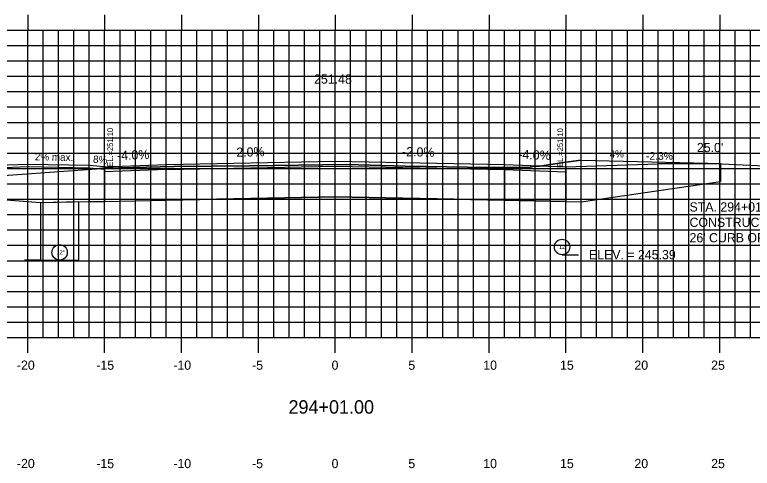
# Model space of a CAD drawing. Extents: x 859129 to 859299, y 366268 to 366378.
# Drawn here: x 859191.61 to 859239.58, y 366298.73 to 366328.24 of the extents above; entities that cross this region are included whole.
import ezdxf

# ---------------------------------------------------------------- set-up
doc = ezdxf.new("R2010")
doc.units = 0
for name, color, linetype in [('ANNOTATION', 7, 'Continuous'), ('D_Roadway_Centerline_Text', 7, 'Continuous'), ('D_Roadway_Drive_Gravel_LT', 7, 'Continuous'), ('D_Roadway_Drive_Gravel_RT', 7, 'Continuous'), ('D_Roadway_Drive_SubGrade', 7, 'Continuous'), ('D_Roadway_Edge_Shoulder', 7, 'Continuous'), ('D_Roadway_SubGrade', 7, 'Continuous'), ('D_Text_Monospaced', 7, 'Continuous'), ('D_Text_Standard', 7, 'Continuous'), ('H_V ANNOTATION', 7, 'Continuous'), ('JUNK COM EXC', 7, 'Continuous'), ('junk strct exc', 7, 'Continuous'), ('MAJOR', 7, 'Continuous'), ('MINOR', 7, 'Continuous'), ('PDRAIN', 7, 'Continuous'), ('S_Roadway_Centerline', 7, 'Continuous')]:
    doc.layers.add(name, color=color, linetype=linetype)

msp = doc.modelspace()

# ---------------------------------------------------------------- linework, layer by layer
at = {"layer": 'D_Roadway_Drive_Gravel_LT'}
for p, q in [((859192.463, 366318.501), (859189.459, 366318.381)), ((859192.47, 366318.334), (859189.459, 366318.214)), ((859196.455, 366318.254), (859192.455, 366318.334)), ((859196.463, 366318.421), (859192.463, 366318.501)), ((859197.459, 366318.174), (859196.455, 366318.254)), ((859197.463, 366318.341), (859196.463, 366318.421)), ((859197.463, 366318.341), (859197.463, 366318.007))]:
    msp.add_line(p, q, dxfattribs=at)
at = {"layer": 'D_Roadway_Drive_Gravel_RT'}
msp.add_line((859227.462, 366318.341), (859233.462, 366318.546), dxfattribs=at)
at = {"layer": 'D_Roadway_Drive_SubGrade'}
for p, q in [((859237.508, 366318.546), (859233.462, 366318.546)), ((859237.508, 366318.546), (859237.508, 366317.379)), ((859228.462, 366316.068), (859237.508, 366317.379)), ((859193.284, 366316.004), (859184.612, 366316.674)), ((859197.459, 366316.087), (859193.284, 366316.004)), ((859227.462, 366316.088), (859228.462, 366316.068))]:
    msp.add_line(p, q, dxfattribs=at)
at = {"layer": 'D_Roadway_Edge_Shoulder'}
msp.add_line((859227.463, 366318.341), (859227.464, 366318.007), dxfattribs=at)
msp.add_lwpolyline([(859197.463, 366318.341), (859201.463, 366318.501), (859212.463, 366318.721), (859223.463, 366318.501), (859227.462, 366318.341)], dxfattribs=at)
at = {"layer": 'D_Roadway_SubGrade'}
for points in [[(859201.463, 366318.167), (859197.463, 366318.007), (859197.463, 366316.087), (859201.463, 366316.167)], [(859201.463, 366316.167), (859201.463, 366318.167), (859212.463, 366318.387), (859223.463, 366318.167), (859223.463, 366316.167), (859212.463, 366316.387)], [(859223.463, 366318.167), (859227.464, 366318.007), (859227.464, 366316.087), (859223.463, 366316.167)]]:
    msp.add_lwpolyline(points, close=True, dxfattribs=at)
at = {"layer": 'D_Text_Standard'}
for points in [[(859227.212, 366312.626), (859227.599, 366312.626), (859228.279, 366312.626)], [(859193.284, 366312.276), (859192.927, 366312.276), (859192.247, 366312.276)]]:
    msp.add_lwpolyline(points, dxfattribs=at)
at = {"layer": 'JUNK COM EXC'}
msp.add_lwpolyline([(859228.456, 366318.772), (859228.452, 366318.772), (859227.301, 366318.615), (859225.757, 366318.383), (859225.438, 366318.377), (859225.019, 366318.299), (859223.494, 366318.328), (859222.407, 366318.303), (859217.013, 366318.39), (859213.218, 366318.491), (859206.908, 366318.407), (859201.989, 366318.366), (859197.482, 366318.259), (859197.347, 366318.256), (859197.329, 366318.256), (859196.931, 366318.222), (859196.459, 366318.189), (859196.459, 366316.067), (859201.463, 366316.167), (859212.463, 366316.387), (859223.463, 366316.167), (859228.462, 366316.068), (859228.456, 366318.772)], dxfattribs=at)
at = {"layer": 'junk strct exc'}
msp.add_lwpolyline([(859193.284, 366316.004), (859193.284, 366312.276), (859195.784, 366312.276), (859195.784, 366316.054)], close=True, dxfattribs=at)
at = {"layer": 'MAJOR'}
for p, q in [((859192.462, 366328.238), (859192.462, 366327.236)), ((859197.462, 366328.238), (859197.462, 366327.236)), ((859202.462, 366328.238), (859202.462, 366327.236)), ((859207.462, 366328.238), (859207.462, 366327.236)), ((859212.462, 366328.238), (859212.462, 366327.236)), ((859217.462, 366328.238), (859217.462, 366327.236)), ((859222.462, 366328.238), (859222.462, 366327.236)), ((859227.462, 366328.238), (859227.462, 366327.236)), ((859232.462, 366328.238), (859232.462, 366327.236)), ((859237.462, 366328.238), (859237.462, 366327.236)), ((859142.462, 366327.236), (859282.462, 366327.236)), ((859142.462, 366327.236), (859282.462, 366327.236)), ((859192.462, 366307.236), (859192.462, 366327.236)), ((859197.462, 366307.236), (859197.462, 366327.236)), ((859202.462, 366307.236), (859202.462, 366327.236)), ((859207.462, 366307.236), (859207.462, 366327.236)), ((859212.462, 366307.236), (859212.462, 366327.236)), ((859217.462, 366307.236), (859217.462, 366327.236)), ((859222.462, 366307.236), (859222.462, 366327.236)), ((859227.462, 366307.236), (859227.462, 366327.236)), ((859232.462, 366307.236), (859232.462, 366327.236)), ((859237.462, 366307.236), (859237.462, 366327.236)), ((859142.462, 366322.236), (859282.462, 366322.236)), ((859142.462, 366317.236), (859282.462, 366317.236)), ((859142.462, 366312.236), (859282.462, 366312.236)), ((859142.462, 366307.236), (859282.462, 366307.236)), ((859142.462, 366307.236), (859282.462, 366307.236)), ((859192.462, 366306.234), (859192.462, 366307.236)), ((859197.462, 366306.234), (859197.462, 366307.236)), ((859202.462, 366306.234), (859202.462, 366307.236)), ((859207.462, 366306.234), (859207.462, 366307.236)), ((859212.462, 366306.234), (859212.462, 366307.236)), ((859217.462, 366306.234), (859217.462, 366307.236)), ((859222.462, 366306.234), (859222.462, 366307.236)), ((859227.462, 366306.234), (859227.462, 366307.236)), ((859232.462, 366306.234), (859232.462, 366307.236)), ((859237.462, 366306.234), (859237.462, 366307.236))]:
    msp.add_line(p, q, dxfattribs=at)
at = {"layer": 'MINOR'}
for p, q in [((859193.462, 366307.236), (859193.462, 366327.236)), ((859194.462, 366307.236), (859194.462, 366327.236)), ((859195.462, 366307.236), (859195.462, 366327.236)), ((859196.462, 366307.236), (859196.462, 366327.236)), ((859198.462, 366307.236), (859198.462, 366327.236)), ((859199.462, 366307.236), (859199.462, 366327.236)), ((859200.462, 366307.236), (859200.462, 366327.236)), ((859201.462, 366307.236), (859201.462, 366327.236)), ((859203.462, 366307.236), (859203.462, 366327.236)), ((859204.462, 366307.236), (859204.462, 366327.236)), ((859205.462, 366307.236), (859205.462, 366327.236)), ((859206.462, 366307.236), (859206.462, 366327.236)), ((859208.462, 366307.236), (859208.462, 366327.236)), ((859209.462, 366307.236), (859209.462, 366327.236)), ((859210.462, 366307.236), (859210.462, 366327.236)), ((859211.462, 366307.236), (859211.462, 366327.236)), ((859213.462, 366307.236), (859213.462, 366327.236)), ((859214.462, 366307.236), (859214.462, 366327.236)), ((859215.462, 366307.236), (859215.462, 366327.236)), ((859216.462, 366307.236), (859216.462, 366327.236)), ((859218.462, 366307.236), (859218.462, 366327.236)), ((859219.462, 366307.236), (859219.462, 366327.236)), ((859220.462, 366307.236), (859220.462, 366327.236)), ((859221.462, 366307.236), (859221.462, 366327.236)), ((859223.462, 366307.236), (859223.462, 366327.236)), ((859224.462, 366307.236), (859224.462, 366327.236)), ((859225.462, 366307.236), (859225.462, 366327.236)), ((859226.462, 366307.236), (859226.462, 366327.236)), ((859228.462, 366307.236), (859228.462, 366327.236)), ((859229.462, 366307.236), (859229.462, 366327.236)), ((859230.462, 366307.236), (859230.462, 366327.236)), ((859231.462, 366307.236), (859231.462, 366327.236)), ((859233.462, 366307.236), (859233.462, 366327.236)), ((859234.462, 366307.236), (859234.462, 366327.236)), ((859235.462, 366307.236), (859235.462, 366327.236)), ((859236.462, 366307.236), (859236.462, 366327.236)), ((859238.462, 366307.236), (859238.462, 366327.236)), ((859239.462, 366307.236), (859239.462, 366327.236)), ((859142.462, 366326.236), (859282.462, 366326.236)), ((859142.462, 366325.236), (859282.462, 366325.236)), ((859142.462, 366324.236), (859282.462, 366324.236)), ((859142.462, 366323.236), (859282.462, 366323.236)), ((859142.462, 366321.236), (859282.462, 366321.236)), ((859142.462, 366320.236), (859282.462, 366320.236)), ((859142.462, 366319.236), (859282.462, 366319.236)), ((859142.462, 366318.236), (859282.462, 366318.236)), ((859142.462, 366316.236), (859282.462, 366316.236)), ((859142.462, 366315.236), (859282.462, 366315.236)), ((859142.462, 366314.236), (859282.462, 366314.236)), ((859142.462, 366313.236), (859282.462, 366313.236)), ((859142.462, 366311.236), (859282.462, 366311.236)), ((859142.462, 366310.236), (859282.462, 366310.236)), ((859142.462, 366309.236), (859282.462, 366309.236)), ((859142.462, 366308.236), (859282.462, 366308.236))]:
    msp.add_line(p, q, dxfattribs=at)
at = {"layer": 'PDRAIN'}
msp.add_lwpolyline([(859193.284, 366316.004), (859193.284, 366312.276), (859195.784, 366312.276), (859195.784, 366316.054)], dxfattribs=at)
for centre in [(859227.212, 366313.126), (859194.534, 366312.776)]:
    msp.add_circle(centre, 0.5, dxfattribs=at)
at = {"layer": 'S_Roadway_Centerline'}
msp.add_lwpolyline([(859169.832, 366316.983), (859171.943, 366316.928), (859172.963, 366316.992), (859184.977, 366317.349), (859189.338, 366317.678), (859196.931, 366318.222), (859197.329, 366318.256), (859197.347, 366318.256), (859197.482, 366318.259), (859201.989, 366318.366), (859206.908, 366318.407), (859213.218, 366318.491), (859217.013, 366318.39), (859222.407, 366318.303), (859223.494, 366318.328), (859225.019, 366318.299), (859225.438, 366318.377), (859225.757, 366318.383), (859227.301, 366318.615), (859228.452, 366318.772), (859236.7, 366318.584), (859249.126, 366317.989), (859257.602, 366317.315), (859264.492, 366316.922)], dxfattribs=at)

# ---------------------------------------------------------------- texts
at = {"layer": 'ANNOTATION'}
for s, rotation, p in [('-2.0%', 1.1458, (859205.766, 366318.987)), ('-2.0%', 358.8542, (859216.806, 366319.034)), ('-4.0%', 2.2906, (859198.28, 366318.774)), ('-4.0%', 357.7097, (859224.359, 366318.865))]:
    msp.add_text(s, height=0.6, rotation=rotation, dxfattribs=at).set_placement(p)
for s, p in [('STA. 294+01 RT.', (859235.502, 366315.434)), ('CONSTRUCT GRAVEL ENTRANCE', (859235.502, 366314.432)), ("26' CURB OPENING", (859235.502, 366313.43))]:
    msp.add_text(s, height=0.6, dxfattribs=at).set_placement(p)
at = {"layer": 'D_Roadway_Centerline_Text'}
msp.add_text('251.48', height=0.6, dxfattribs=at).set_placement((859211.084, 366323.753))
at = {"layer": 'D_Roadway_Drive_Gravel_LT'}
for s, rotation, p in [('2% max.', 358.8078, (859192.917, 366318.771)), ('8%', 355.4261, (859196.694, 366318.608))]:
    msp.add_text(s, height=0.48, rotation=rotation, dxfattribs=at).set_placement(p)
at = {"layer": 'D_Roadway_Drive_Gravel_RT'}
msp.add_text('4%', height=0.48, rotation=2.2906, dxfattribs=at).set_placement((859230.311, 366318.921))
at = {"layer": 'D_Text_Monospaced'}
msp.add_text('-2.3%', height=0.5, rotation=0.3253, dxfattribs=at).set_placement((859232.673, 366318.796))
at = {"layer": 'D_Text_Standard'}
for p in [(859198.006, 366318.205), (859227.275, 366318.187)]:
    msp.add_text(' EL.=251.10', height=0.36848, rotation=90, dxfattribs=at).set_placement(p)
for s, p in [("25.0'", (859235.98, 366319.297)), ('ELEV. = 245.39', (859228.959, 366312.326))]:
    msp.add_text(s, height=0.6, dxfattribs=at).set_placement(p)
at = {"layer": 'H_V ANNOTATION'}
for s, height, p in [('-20', 0.6, (859191.755, 366305.136)), ('-15', 0.6, (859196.918, 366305.136)), ('-10', 0.6, (859201.927, 366305.136)), ('-5', 0.6, (859207.052, 366305.136)), ('0', 0.6, (859212.221, 366305.136)), ('5', 0.6, (859217.213, 366305.136)), ('10', 0.6, (859222.087, 366305.136)), ('15', 0.6, (859227.079, 366305.136)), ('20', 0.6, (859231.916, 366305.136)), ('25', 0.6, (859236.908, 366305.136)), ('294+01.00', 0.875, (859209.419, 366302.28)), ('-20', 0.6, (859191.755, 366298.736)), ('-15', 0.6, (859196.918, 366298.736)), ('-10', 0.6, (859201.927, 366298.736)), ('-5', 0.6, (859207.052, 366298.736)), ('0', 0.6, (859212.221, 366298.736)), ('5', 0.6, (859217.213, 366298.736)), ('10', 0.6, (859222.087, 366298.736)), ('15', 0.6, (859227.079, 366298.736)), ('20', 0.6, (859231.916, 366298.736)), ('25', 0.6, (859236.908, 366298.736))]:
    msp.add_text(s, height=height, dxfattribs=at).set_placement(p)
at = {"layer": 'PDRAIN'}
for p in [(859194.343, 366312.652), (859227.021, 366313.002)]:
    msp.add_text('12"', height=0.25, dxfattribs=at).set_placement(p)
at = {"layer": 'S_Roadway_Centerline'}
for s, p in [('C', (859213.213, 366318.491)), ('L', (859213.218, 366318.484))]:
    msp.add_text(s, height=0.0146, dxfattribs=at).set_placement(p)

doc.saveas('drawing.dxf')
